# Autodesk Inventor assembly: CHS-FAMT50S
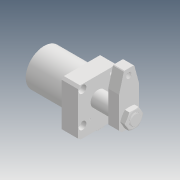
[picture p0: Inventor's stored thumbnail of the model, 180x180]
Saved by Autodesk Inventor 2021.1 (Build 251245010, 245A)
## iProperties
Created: 2019-04
Part Number: CHS-FAMT50S
Description: STEP AP203
Document SubType Name: Assembly
Designer: user
Title: chs-famt50s_asm.STEP
Revision Number: ÈÎºÎ
Sending System: SolidWorks 2017
Preprocessor: SwSTEP 2.0
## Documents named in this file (9)
- D:\Vault_2016\Projekty\Clamptek\Hydraulic\CHS\CHS-50\Inventor\CHS-FAMT50S\CHS-FAMT50S.iam
- D:\Vault_2016\Projekty\Clamptek\Hydraulic\CHS\CHS-50\Inventor\CHS-FAMT50S\M4.ipt
- D:\Vault_2016\Projekty\Clamptek\Hydraulic\CHS\CHS-50\Inventor\CHS-FAMT50S\CHS-50SHSG_6.ipt
- D:\Vault_2016\Projekty\Clamptek\Hydraulic\CHS\CHS-50\Inventor\CHS-FAMT50S\CHS-50SYB_7.ipt
- D:\Vault_2016\Projekty\Clamptek\Hydraulic\CHS\CHS-50\Inventor\CHS-FAMT50S\M20LM_7.ipt
- D:\Vault_2016\Projekty\Clamptek\Hydraulic\CHS\CHS-50\Inventor\CHS-FAMT50S\20·§Ìå.ipt
- D:\Vault_2016\Projekty\Clamptek\Hydraulic\CHS\CHS-50\Inventor\CHS-FAMT50S\20µ÷ËÙ¸Ë.ipt
- D:\Vault_2016\Projekty\Clamptek\Hydraulic\CHS\CHS-50\Inventor\CHS-FAMT50S\hex thin nuts-grades ab-chamfered gb(GB_FASTENER_NUT_STNAB M6-S).ipt
- D:\Vault_2016\Projekty\Clamptek\Hydraulic\CHS\CHS-50\Inventor\CHS-FAMT50S\CHS-FAMT50  BT.ipt
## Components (10 placed, 10 different names)
1. M4_1
2. M4_2
3. M4_3
4. CHS-50SHSG_6_4
5. CHS-50SYB_7_5
6. M20LM_7_6
7. 20·§Ìå_7
8. 20µ÷ËÙ¸Ë_8
9. hex thin nuts-grades ab-chamfered gb(GB_FASTENER_NUT_STNAB M6-S)_9
10. CHS-FAMT50  BT_10
